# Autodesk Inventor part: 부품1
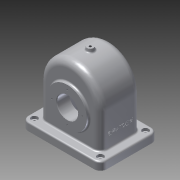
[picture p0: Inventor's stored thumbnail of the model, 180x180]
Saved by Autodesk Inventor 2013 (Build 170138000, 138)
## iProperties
Created: 2016-10
Part Number: 부품1
Material: 알루미늄 6061
Document SubType Name: Modeling
Designer: cad10
Density: 2.71 g/cm^3
Mass: 1165.01 g
Surface Area: 1200.16 cm^2
Volume: 429.894 cm^3
Author: cad10
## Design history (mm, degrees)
sketch "스케치2"
  geometry: L1 (-58, 0)-(58, 0); L2 (58, 0)-(58, -65); L3 (58, -65)-(-58, -65); L4 (-58, -65)-(-58, 0); A1 r 58 centre (0, 0) between (58, 0) and (-58, 0); 1 further point
  constraints: 8 end point, 2 parallel, 2 point on circle, 2 tangent, 1 centre point, 1 coincident, 1 horizontal, 1 perpendicular
  dimensions: "d0" = 65 distance of L3.end L1.start; "d2" = 58 radius of A1
extrude "돌출1" new body sketch "스케치2" distance "d3" = 77; taper "d4" = 0 deg
sketch "스케치3"
  geometry: L1 (116, 0)-(0, 0) reference; L2 (0, 77)-(116, 77) reference; L3 (0, 0)-(0, 77) reference; L4 (-17, 93.5)-(133, 93.5); L5 (133, 93.5)-(133, -16.5); L6 (133, -16.5)-(-17, -16.5); L7 (-17, -16.5)-(-17, 93.5); 1 further point
  constraints: 8 end point, 2 parallel, 1 horizontal, 1 perpendicular
  dimensions: "d5" = 110 distance of L6.end L4.start; "d7" = 150 distance of L4.start L4.end; "d8" = 77 distance between parallel lines of L1 L2 (derived); "d9" = 16.5 distance between parallel lines of L2 L4; "d10" = 17 distance between parallel lines of L3 L7
extrude "돌출2" join sketch "스케치3" distance "d11" = 15; taper "d12" = 0 deg
node "작업 평면1"
fillet "모깎기1" dims "d25" = 3
fillet "모깎기2" dims "d26" = 12
sketch "스케치7"
  geometry: A1 r 9 centre (-5, -81.5) between (-14, -81.5) and (-5, -90.5) reference; A2 r 9 centre (121, -81.5) between (121, -90.5) and (130, -81.5) reference; A3 r 9 centre (121, 4.5) between (130, 4.5) and (121, 13.5) reference; A4 r 9 centre (-5, 4.5) between (-5, 13.5) and (-14, 4.5) reference; 1 further point
hole "구멍2" sketch "스케치7" at (-5, -81.5), (121, -81.5), (121, 4.5), (-5, 4.5) diameter "d27" = 5; stored, may be unused: countersink angle "d31" = 90 deg, drill point angle "d33" = 118 deg; dims "d28" = 10, "d29" = 12, "d30" = 5, "d32" = 46.25
sketch "스케치8"
  geometry: L1 (63, -80)-(-63, -80) reference; C1 r 37.5 at (0, -15); A1 r 58 centre (0, 0) between (58, 0) and (-58, 0) reference
  constraints: 1 centre point, 1 vertical alignment
  dimensions: "d34" = 65 distance from line of L1 C1.centre; "d35" = 75 diameter of C1
extrude "돌출3" join sketch "스케치8" distance "d36" = 5; taper "d37" = 0 deg
sketch "스케치9"
  geometry: L1 (63, -80)-(-63, -80) reference; C1 r 31 at (0, -15); A1 r 58 centre (0, 0) between (58, 0) and (-58, 0) reference
  constraints: 1 centre point, 1 vertical alignment
  dimensions: "d38" = 65 distance from line of L1 C1.centre; "d39" = 62 diameter of C1
extrude "돌출4" join sketch "스케치9" distance "d40" = 10; taper "d41" = 0 deg
sketch "스케치10"
  geometry: C1 r 37.5 at (0, 0) reference; C2 r 20 at (0, 0); 1 further point
  constraints: 1 centre point, 1 coincident
  dimensions: "d42" = 40 diameter of C2
extrude "돌출5" cut sketch "스케치10" stored distance "d44" = 10; taper "d45" = 0 deg
fillet "모깎기3" dims "d49" = 13
sketch "스케치14"
  geometry: L1 (-17, -4.5)-(-17, 81.5) reference; C1 r 6 at (58, 38); 1 further point
  constraints: 1 centre point
  dimensions: "d50" = 38 distance of C1.centre point (58, 0); "d51" = 75 distance from line of L1 C1.centre; "d52" = 12 diameter of C1
extrude "돌출6" join sketch "스케치14" stored distance "d53" = 10; taper "d54" = 10 deg
sketch "스케치15"
  geometry: C1 r 6 at (0, 0) reference; 2 further points
  constraints: 1 coincident
hole "구멍3" sketch "스케치15" at (0, 0) diameter "d55" = 4.459; stored, may be unused: countersink angle "d59" = 90 deg, drill point angle "d61" = 118 deg; dims "d56" = 20, "d57" = 4, "d58" = 2, "d60" = 8
sketch "스케치17" dims "d67" = 58
  geometry: C1 r 20 at (0, 0) reference; C2 r 37.5 at (0, 0) reference; 3 further points
  constraints: 2 horizontal alignment, 1 coincident, 2 other
hole "구멍4" sketch "스케치17" at (-29, 0) diameter "d69" = 2.459; stored, may be unused: countersink angle "d73" = 90 deg, drill point angle "d75" = 118 deg; dims "d70" = 6, "d71" = 4, "d72" = 2, "d74" = 8
sketch "스케치18" dims "d79" = 52
  geometry: C1 r 20 at (0, 0) reference; C2 r 31 at (0, 0) reference; 3 further points
  constraints: 2 vertical alignment, 1 coincident, 2 other
hole "구멍5" sketch "스케치18" at (0, 26) diameter "d81" = 2.459; stored, may be unused: countersink angle "d85" = 90 deg, drill point angle "d87" = 118 deg; dims "d82" = 6, "d83" = 4, "d84" = 2, "d86" = 8
node "작업 평면3"
sketch "스케치20"
  geometry: L1 (-63, -65)-(63, -65) reference; L2 (-58, -50)-(-58, 15) reference; C1 r 28 at (0, 0); 1 further point
  constraints: 1 centre point
  dimensions: "d94" = 56 diameter of C1; "d96" = 65 distance from line of L1 C1.centre; "d97" = 58 distance from line of L2 C1.centre
extrude "돌출7" cut sketch "스케치20" distance "d98" = 53; taper "d99" = 0 deg
sketch "스케치22"
  geometry: L1 (-52, 15)-(52, 15); L2 (52, 15)-(52, -65); L3 (52, -65)-(-52, -65); L4 (-52, -65)-(-52, 15); L5 (-63, -65)-(63, -65) reference; A1 r 52 centre (0, 15) between (52, 15) and (-52, 15); 1 further point
  constraints: 8 end point, 2 parallel, 2 point on circle, 1 centre point, 1 coincident, 1 horizontal, 1 perpendicular, 1 point on line, 1 tangent
  dimensions: "d100" = 104 diameter of A1
extrude "돌출8" cut sketch "스케치22" distance "d103" = 67; taper "d104" = 0 deg
chamfer "모따기1" distance "d105" = 1; stored, may be unused: second distance "d106" = 2, angle "d107" = 45 deg
sketch "스케치23"
  geometry: L1 (13, 58)-(24.747, 72); L2 (-15, 90.791)-(-15, -25.793); L3 (-80, 5)-(-80, 72) reference; L4 (-80, 72)-(0, 72) reference; L5 (13, 58)-(-15, 58); L6 (-15, 58)-(-15, 72); L7 (-15, 72)-(24.747, 72); L8 (-15, 72)-(24.747, 72); 1 further point
  constraints: 12 end point, 3 point on line, 2 perpendicular, 1 collinear
  dimensions: "d110" = 65 distance between parallel lines of L3 L2; "d115" = 28 distance of L1.start L5.end; "d116" = 50 deg angle of L5 L1; "d117" = 14 distance between parallel lines of L4 L5
revolve "회전1" sketch "스케치23" stored, may be unused: angle "d118" = 90 deg
fillet "모깎기4" dims "d119" = 8
fillet "모깎기5" dims "d120" = 3
sketch "스케치24"
  geometry: C1 r 20 at (0, 0) reference; C2 r 20 at (0, 0); 1 further point
  constraints: 1 centre point, 1 coincident, 1 concentric
extrude "돌출9" cut sketch "스케치24" distance "d121" = 67; taper "d122" = 0 deg
fillet "모깎기6" dims "d125" = 3
node "작업 평면4"
sketch "스케치26"
  geometry: L1 (68.5, -80)-(-17.5, -80) reference; L2 (-13, 0)-(-13, -62) reference; 2 further points
  constraints: 1 other
  dimensions: "d132" = 40 distance from line of L1 point (25.5, -40); "d133" = 38.5 distance from line of L2 point (25.5, -40)
feature "엠보싱1" sketch "스케치26" dims "d129" = 0.5, "d130" = 0
fillet "모깎기7" dims "d131" = 3
node "솔리드1"
pattern_circular "원형 패턴1" dims angle "d77" = 360 deg
pattern_circular "원형 패턴2" dims angle "d89" = 360 deg
other parameters: "d13" = -144, "d126" = 15.5
